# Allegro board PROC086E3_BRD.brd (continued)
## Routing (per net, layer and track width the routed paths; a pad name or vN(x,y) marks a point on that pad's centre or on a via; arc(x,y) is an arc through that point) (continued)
VOUT0_DATA1: length 63.6
  TOP w0.178: v1(73.28,137.35) 72.75,137.88 72.75,139.28 72.28,139.75 U11.4 ; v1(80.02,128.91) 80.02,106.18 81.2,105.01 J1.43
  BOTTOM w0.178: v1(73.28,137.35) 74.47,136.15 75.38,136.15 75.54,136 75.54,134.96 76.02,134.48 78.66,134.48 78.84,134.65 78.84,135.06 78.66,135.24 76.38,135.24 76.2,135.42 76.2,135.84 76.36,136 79.32,136 79.5,135.82 79.5,134.58 78.71,133.79 78.71,133.47 78.56,133.32 76.74,133.32 76.35,132.93 76.35,131.96 76.53,131.78 76.8,131.78 76.96,131.94 76.96,132.11 77.14,132.29 77.49,132.29 77.65,132.14 77.65,131.22 77.8,131.07 78.02,131.07 78.18,131.22 78.18,132.63 78.34,132.78 78.66,132.78 78.84,132.61 78.84,130.88 78.22,130.26 78.22,129.65 78.4,129.47 79.46,129.47 v1(80.02,128.91)
VOUT0_DATA2: length 63.7
  TOP w0.178: U11.6 v1(73.28,138.37) ; J1.41 81.11,104.51 79.5,106.12 79.5,129.48 v1(78.98,130.01)
  BOTTOM w0.178: v1(78.98,130.01) 79.4,130.42 79.4,133.61 79.55,133.76 82.73,133.76 82.91,133.94 82.91,134.53 82.4,135.03 80.49,135.03 80.31,135.21 80.31,136.56 80.14,136.74 75.46,136.74 73.79,138.41 73.79,142.19 73.43,142.55 72.14,142.55 71.96,142.38 71.96,141.91 72.49,141.38 72.49,140.52 71.96,139.99 71.96,138.54 72.14,138.37 v1(73.28,138.37)
VOUT0_DATA3: length 63.7
  TOP w0.178: J1.45 81.43,105.51 80.54,106.4 80.54,131.88 80.7,132.03 81.86,132.03 82.02,132.19 82.02,132.41 81.86,132.57 80.8,132.57 80.37,133 79.1,133 78.92,132.82 78.92,132.51 79.07,132.35 79.83,132.35 79.98,132.2 79.98,131.97 79.83,131.82 79.07,131.82 78.92,131.66 78.92,130.72 79.1,130.54 79.84,130.54 80.02,130.36 v1(80.02,130.01) ; U11.9 v1(74.78,138.37)
  BOTTOM w0.178: v1(74.78,138.37) 75.36,137.78 76.3,137.78 76.76,137.32 79.35,137.32 79.81,137.78 80.9,137.78 81.08,137.6 81.08,135.72 81.25,135.54 82.65,135.54 83.97,134.22 83.97,133.49 83.64,133.16 80.2,133.16 80.02,132.98 v1(80.02,130.01)
VOUT0_DATA4: length 63.4
  TOP w0.178: J1.47 82.57,106.01 80.95,107.63 80.95,128.89 v1(81.06,129) ; U11.11 v1(75.78,138.37)
  BOTTOM w0.178: v1(81.06,129) 81.06,129.97 80.57,130.46 80.57,131.83 81.33,132.6 83.87,132.6 84.94,133.66 84.94,134.12 82.4,136.66 82.4,137.73 81.94,138.18 79.4,138.18 78.94,137.73 77.27,137.73 77.09,137.9 77.09,141.61 76.64,142.06 74.82,142.06 74.27,141.51 74.27,140.37 74.45,140.19 76.25,140.19 76.4,140.03 76.4,139.81 76.25,139.66 74.74,139.66 74.58,139.5 74.58,139.28 74.74,139.12 76.25,139.12 76.4,138.97 76.4,138.54 76.23,138.37 v1(75.78,138.37)
VOUT0_DATA5: length 63.9
  TOP w0.178: U11.13 76.78,139.16 76.85,139.09 76.85,110.85 76.81,110.85 70.28,104.33 70.28,100.29 70.56,100.01 70.88,100.01 71.04,99.85 71.04,99.02 71.19,98.87 71.41,98.87 71.57,99.02 71.57,99.85 71.73,100.01 71.95,100.01 72.1,99.85 72.1,99.02 72.26,98.87 72.48,98.87 72.64,99.02 72.64,99.85 72.79,100.01 73.01,100.01 73.17,99.85 73.17,99.02 73.33,98.87 73.55,98.87 73.7,99.02 73.7,99.85 73.86,100.01 J1.23
VOUT0_DATA6: length 63.5
  TOP w0.178: U11.15 v1(77.78,138.37) ; J1.49 82.73,106.51 81.36,107.87 81.36,128.11 81.69,128.43 81.69,129.32 81.06,129.94 v1(81.06,131.29)
  BOTTOM w0.178: v1(81.06,131.29) 81.31,131.53 83.21,131.53 83.57,131.17 84.53,131.17 84.83,131.47 84.83,131.69 84.51,132 84.51,132.32 84.79,132.6 85.14,132.6 85.42,132.32 85.67,132.32 86.31,132.95 86.31,133.56 83.06,136.81 83.06,141 82.88,141.18 81.53,141.18 81.35,141 81.35,140.65 81.51,140.5 82.29,140.5 82.45,140.34 82.45,140.04 82.27,139.86 81.51,139.86 81.35,139.7 81.35,139.48 81.53,139.3 82.37,139.3 82.53,139.15 82.53,138.92 82.3,138.69 81,138.69 80.82,138.87 80.82,141.07 80.64,141.24 79.98,141.24 79.81,141.07 79.81,139.07 79.63,138.9 78.38,138.9 77.85,138.37 v1(77.78,138.37)
VOUT0_DATA7: length 63.8
  TOP w0.178: U11.18 79.28,138.62 77.23,136.58 77.23,110.59 70.76,104.12 70.76,100.68 70.94,100.51 71.26,100.51 71.42,100.66 71.42,103.46 71.57,103.61 71.79,103.61 71.95,103.46 71.95,100.66 72.11,100.51 J1.25
VOUT0_DATA8: length 63.4
  TOP w0.178: U11.21 80.78,139.48 77.64,136.35 77.64,110.34 72.49,105.19 72.49,101.18 72.67,101.01 73.16,101.01 73.31,101.16 73.31,104.93 73.47,105.09 73.69,105.09 73.85,104.93 73.85,101.16 74,101.01 J1.27
VOUT0_DATA9: length 63.6
  TOP w0.178: J1.29 75.79,101.51 75.63,101.66 75.63,103.48 75.48,103.64 75.25,103.64 75.1,103.48 75.1,101.66 74.94,101.51 74.62,101.51 74.32,101.81 74.32,106.26 78.05,109.98 78.05,133.86 78.51,134.32 79.18,134.32 79.33,134.48 79.33,137.19 79.49,137.35 79.71,137.35 79.87,137.19 79.87,134.48 80.02,134.32 80.42,134.32 80.75,134.65 80.75,138.26 81.78,139.29 U11.23
VOUT0_DATA10: length 63.6
  TOP w0.178: U11.25 82.78,136.86 81.76,135.85 81.76,133.76 81.43,133.43 78.83,133.43 78.45,133.05 78.45,109.35 76.3,107.2 76.3,106.4 76.15,106.25 75.16,106.25 75.01,106.09 75.01,105.87 75.16,105.71 76.15,105.71 76.3,105.56 76.3,105.34 76.15,105.18 75.16,105.18 75.01,105.02 75.01,104.8 75.16,104.65 76.15,104.65 76.3,104.49 76.3,102.19 76.5,101.99 76.82,101.99 76.98,102.15 76.98,105.82 77.13,105.98 77.36,105.98 77.51,105.82 77.51,102.16 77.67,102.01 J1.31
VOUT0_DATA11: length 63.6
  TOP w0.178: U11.27 v1(83.78,138.37) ; J1.14 94.45,97.51 99.82,102.88 v1(99.82,129.9)
  BOTTOM w0.178: v1(99.82,129.9) 100.23,130.31 100.23,131.02 100.08,131.17 99.72,131.17 99.57,131.02 99.57,130.62 99.01,130.06 90.53,130.06 84.79,135.8 84.79,136.66 84.94,136.81 84.94,138.13 84.71,138.37 v1(83.78,138.37)
VOUT0_DATA12: length 63.8
  TOP w0.178: U12.2 v1(86.72,138.37) ; v1(98.77,130.7) 98.77,103.45 93.83,98.51 J1.18
  BOTTOM w0.178: v1(98.77,130.7) 90.84,130.7 86.89,134.66 86.89,134.91 88.29,136.3 88.29,136.81 87.83,137.27 87.58,137.27 87.39,137.08 87.39,136.86 87.58,136.67 87.58,136.45 87.42,136.29 87.2,136.29 86.94,136.56 86.71,136.56 86.46,136.3 86.46,136.05 86.67,135.84 86.67,135.62 86.51,135.47 86.18,135.47 85.5,136.15 85.5,136.41 86.94,137.85 86.94,138.07 86.72,138.28 v1(86.72,138.37)
VOUT0_DATA13: length 63.8
  TOP w0.178: U12.4 v1(87.72,138.37) ; J1.16 94.04,98.01 99.29,103.26 v1(99.29,131.73)
  BOTTOM w0.178: v1(99.29,131.73) 99.19,131.63 92.71,131.63 89.62,134.72 89.4,134.72 89.15,134.48 89.15,134.21 90.69,132.68 90.69,132.46 90.5,132.26 90.25,132.26 88.49,134.02 88.49,134.56 89.02,135.1 89.02,135.32 88.7,135.64 88.7,135.9 89.32,136.52 89.32,136.77 v1(87.72,138.37)
VOUT0_DATA14: length 63.8
  TOP w0.178: U12.6 v1(88.72,138.37) ; v1(100.34,132.76) 100.34,102.46 94.39,96.51 J1.10
  BOTTOM w0.178: v1(100.34,132.76) 94.63,132.76 91.32,136.07 91.1,136.07 90.8,135.77 90.8,135.52 91.81,134.51 91.81,134.29 91.57,134.04 91.31,134.04 90.07,135.29 90.07,135.79 90.72,136.45 90.72,136.67 89.02,138.37 v1(88.72,138.37)
VOUT0_DATA15: length 63.7
  TOP w0.178: J1.8 94.6,96.01 100.86,102.27 v1(100.86,133.79) ; U12.9 v1(90.22,138.37)
  BOTTOM w0.178: v1(90.22,138.37) 90.24,138.37 93.07,135.54 94.28,135.54 94.54,135.29 94.54,134.48 95.07,133.94 97.92,133.94 98.08,134.1 98.08,136.34 98.35,136.61 99.26,136.61 99.68,136.19 99.68,134.12 99.86,133.94 100.71,133.94 v1(100.86,133.79)
VOUT0_DATA16: length 63.8
  TOP w0.178: U12.11 v1(91.22,138.37) ; v1(96.19,136.41) 97,135.59 97,106.76 94.75,104.51 J1.42
  BOTTOM w0.178: v1(96.19,136.41) 93.68,136.41 93.5,136.58 93.5,139.96 93.32,140.14 91.18,140.14 91.02,140.3 91.02,141.03 90.87,141.18 90.65,141.18 90.49,141.03 90.49,140.3 90.33,140.14 90.11,140.14 89.96,140.3 89.96,141.03 89.8,141.18 89.58,141.18 89.42,141.03 89.42,140.3 89.27,140.14 85.62,140.14 85.45,139.96 85.45,139.51 85.62,139.33 91.03,139.33 91.22,139.14 v1(91.22,138.37)
VOUT0_DATA17: length 63.6
  TOP w0.178: U12.13 92.22,137.46 92.06,137.3 90.5,137.3 90.35,137.14 90.35,136.92 90.5,136.77 92.06,136.77 92.22,136.61 92.22,136.39 92.06,136.23 90.5,136.23 90.35,136.08 90.35,135.86 90.5,135.7 92.06,135.7 92.22,135.54 92.22,135.32 92.06,135.17 90.5,135.17 90.35,135.01 90.35,134.79 90.5,134.63 92.06,134.63 92.22,134.48 92.22,134.26 92.06,134.1 90.5,134.1 90.35,133.94 90.35,133.72 90.5,133.57 92.06,133.57 92.22,133.41 92.22,133.19 92.06,133.03 90.5,133.03 90.35,132.88 90.35,132.66 90.5,132.5 92.06,132.5 92.22,132.34 92.22,132.12 92.06,131.97 90.5,131.97 90.35,131.81 90.35,131.59 90.5,131.43 92.06,131.43 92.22,131.28 92.22,131.06 92.06,130.9 90.5,130.9 90.35,130.74 90.35,130.52 90.5,130.37 92.06,130.37 92.22,130.21 92.22,129.81 92.46,129.57 94.89,129.57 95.2,129.27 95.2,107.79 93.92,106.51 J1.50
VOUT0_DATA18: length 63.7
  TOP w0.178: J1.46 94.34,105.51 96.14,107.31 96.14,134.83 95.89,135.09 95.22,135.09 95.05,134.91 95.05,130.26 94.82,130.03 92.89,130.03 92.71,130.21 92.71,130.96 92.87,131.12 94.18,131.12 94.34,131.28 94.34,131.5 94.18,131.65 92.87,131.65 92.71,131.81 92.71,132.03 92.87,132.19 94.18,132.19 94.34,132.34 94.34,132.56 94.18,132.72 92.87,132.72 92.71,132.88 92.71,133.1 92.87,133.25 94.18,133.25 94.34,133.41 94.34,133.63 94.18,133.79 92.87,133.79 92.71,133.94 92.71,134.16 92.87,134.32 94.18,134.32 94.34,134.48 94.34,134.7 94.18,134.85 92.87,134.85 92.71,135.01 92.71,138.74 93.22,139.25 U12.15
VOUT0_DATA19: length 63.7
  TOP w0.178: v1(97.61,128.28) 97.43,128.46 97.43,136.91 94.72,139.63 U12.18 ; J1.40 v1(92.64,104.01)
  BOTTOM w0.178: v1(92.64,104.01) 93.74,104.01 97.43,107.7 97.43,118.06 97.28,118.21 96.19,118.21 96.04,118.37 96.04,118.59 96.19,118.74 97.28,118.74 97.43,118.9 97.43,119.12 97.28,119.28 96.19,119.28 96.04,119.43 96.04,119.66 96.19,119.81 97.28,119.81 97.43,119.97 97.43,120.19 97.28,120.35 96.19,120.35 96.04,120.5 96.04,120.72 96.19,120.88 97.28,120.88 97.43,121.03 97.43,121.26 97.28,121.41 96.19,121.41 96.04,121.57 96.04,121.79 96.19,121.95 97.28,121.95 97.43,122.1 97.43,122.32 97.28,122.48 96.19,122.48 96.04,122.63 96.04,122.86 96.19,123.01 97.28,123.01 97.43,123.17 97.43,123.39 97.28,123.55 96.19,123.55 96.04,123.7 96.04,123.92 96.19,124.08 97.28,124.08 97.43,124.24 97.43,124.46 97.28,124.61 96.19,124.61 96.04,124.77 96.04,124.99 96.19,125.15 97.28,125.15 97.43,125.3 97.43,125.52 97.28,125.68 96.19,125.68 96.04,125.84 96.04,126.06 96.19,126.21 97.28,126.21 97.43,126.37 97.43,126.59 97.28,126.75 96.19,126.75 96.04,126.9 96.04,127.12 96.19,127.28 97.28,127.28 97.43,127.44 97.43,128.1 v1(97.61,128.28)
VOUT0_DATA20: length 63.8
  TOP w0.178: U12.21 v1(96.22,139.53) ; v1(96.22,137.4) 95.63,136.81 95.63,136.05 96.57,135.11 96.57,107.04 94.54,105.01 J1.44
  BOTTOM w0.178: v1(96.22,139.53) 96.22,144.53 95.71,145.04 89.48,145.04 89.31,144.86 89.31,144.64 89.46,144.48 94.64,144.48 95.2,143.92 95.2,141.44 95.5,141.13 95.5,138.84 96.22,138.13 96.22,137.4 v1(96.22,137.4)
VOUT0_DATA21: length 63.8
  TOP w0.178: J1.48 94.13,106.01 95.63,107.51 v1(95.63,134.5) ; U12.23 v1(97.22,139.53)
  BOTTOM w0.178: v1(97.22,139.53) 97.22,146.13 97.37,146.29 98.04,146.29 98.22,146.11 98.22,146.02 98.38,145.87 99.26,145.87 99.42,145.71 99.42,145.49 99.26,145.33 98.38,145.33 98.18,145.13 98.18,142.32 98.38,142.13 100.05,142.13 100.2,141.97 100.2,141.75 100.05,141.59 98.38,141.59 98.22,141.44 98.22,141.21 98.38,141.06 100.05,141.06 100.2,140.9 100.2,140.68 100.05,140.52 98.38,140.52 98.22,140.37 98.22,139.15 98.04,138.97 97.66,138.97 97.22,138.53 97.22,134.68 97.04,134.5 v1(95.63,134.5)
VOUT0_DATA22: length 63.8
  TOP w0.178: J1.28 92.34,101.01 v1(92.74,101.41) ; U12.25 98.22,139.51 98.27,139.45 98.27,134.25 v1(99.11,133.41)
  BOTTOM w0.178: v1(99.11,133.41) 100.43,133.41 100.86,132.98 100.86,128.13 100.71,127.97 99.83,127.97 99.67,127.82 99.67,127.6 99.83,127.44 100.71,127.44 100.86,127.28 100.86,127.06 100.71,126.91 99.83,126.91 99.67,126.75 99.67,126.53 99.83,126.37 100.71,126.37 100.86,126.22 100.86,126 100.71,125.84 99.83,125.84 99.67,125.68 99.67,125.46 99.83,125.31 100.71,125.31 100.86,125.15 100.86,124.93 100.71,124.77 99.83,124.77 99.67,124.62 99.67,124.4 99.83,124.24 100.71,124.24 100.86,124.08 100.86,123.86 100.71,123.71 99.83,123.71 99.67,123.55 99.67,123.33 99.83,123.17 100.71,123.17 100.86,123.02 100.86,122.8 100.71,122.64 99.83,122.64 99.67,122.48 99.67,122.26 99.83,122.11 100.71,122.11 100.86,121.95 100.86,121.73 100.71,121.57 99.83,121.57 99.67,121.42 99.67,121.19 99.83,121.04 100.71,121.04 100.86,120.88 100.86,120.66 100.71,120.51 99.83,120.51 99.67,120.35 99.67,120.13 99.83,119.97 100.71,119.97 100.86,119.82 100.86,106.84 95.43,101.41 v1(92.74,101.41)
VOUT0_DATA23: length 63.8
  TOP w0.178: U12.27 v1(99.22,139.53) ; v1(97.74,138.24) 97.87,138.11 97.87,129.12 98.3,128.68 98.3,127.77 97.87,127.34 97.87,104.88 94.99,102.01 J1.32
  BOTTOM w0.178: v1(97.74,138.24) 101.07,138.24 101.32,138.49 101.32,146.67 101.14,146.85 100.81,146.85 100.63,146.67 100.63,139.73 100.43,139.53 v1(99.22,139.53)
VOUT0_DE: length 63.6
  TOP w0.178: U10.6 57.71,139.55 59.61,137.65 62.36,137.65 62.69,137.32 62.69,136.74 v1(63.3,136.13) ; J1.34 v1(89.66,102.51)
  L03_SIG1 w0.107: v1(89.66,102.51) 89.27,102.51 87.22,104.55 87.22,115.39 83.77,118.84 77.06,118.84 76.95,118.94 76.95,119.34 76.84,119.44 76.39,119.44 76.28,119.34 76.28,118.94 76.18,118.84 70.45,118.84 69.9,119.39 69.9,123.25 64.75,128.4 64.75,134.67 v1(63.3,136.13)
VOUT0_EXTPCLKIN: length 63.6
  TOP w0.178: J1.21 82.89,99.51 v1(82.85,99.47) ; v1(62.13,136.13) 56.29,136.13 55.71,136.7 U10.2
  L08_SIG2 w0.107: v1(82.85,99.47) 73.56,108.77 73.56,110.44 73.65,110.53 74.23,110.53 74.32,110.63 74.32,110.76 74.23,110.85 73.65,110.85 73.56,110.95 73.56,111.08 73.65,111.17 74.23,111.17 74.32,111.27 74.32,111.4 74.23,111.49 73.65,111.49 73.56,111.59 73.56,111.72 73.65,111.81 74.23,111.81 74.32,111.91 74.32,112.04 74.23,112.13 73.65,112.13 73.56,112.23 73.56,112.36 73.65,112.45 74.23,112.45 74.32,112.55 74.32,112.68 74.23,112.77 73.65,112.77 73.56,112.87 73.56,120.51 71.83,122.23 71.83,122.64 71.02,123.45 70.61,123.45 66.6,127.47 66.6,131.48 62.13,135.95 v1(62.13,136.13)
VOUT0_HSYNC: length 63.6
  TOP w0.178: v1(62.13,137.14) 59.21,137.14 56.72,139.63 56.72,140.68 U10.4 ; J1.12 v1(90.07,97.01)
  L03_SIG1 w0.107: v1(90.07,97.01) 90.17,97.11 90.17,110.45 88.44,112.17 88.44,114.64 83.86,119.23 81.09,119.23 63.8,136.51 63.8,137.32 63.49,137.64 62.62,137.64 v1(62.13,137.14)
VOUT0_PCLK: length 63.7
  TOP w0.178: v1(94.77,102.52) 93.43,102.52 92.94,103.01 J1.36 ; v1(67.46,138.29) 67.46,138.74 68.21,139.49 U10.27
  L03_SIG1 w0.107: v1(94.77,102.52) 94.03,103.26 94.03,123.86 91.9,125.99 91.9,128.79 84.73,135.95 73.76,135.95 73.05,135.24 69.01,135.24 68.33,135.92 68.33,137.42 v1(67.46,138.29)
VOUT0_VSYNC: length 63.8
  TOP w0.178: J1.33 v1(84.03,102.51) ; v1(63.3,137.14) 63.3,137.5 62.76,138.03 60.33,138.03 59.21,139.14 U10.9
  L03_SIG1 w0.107: v1(63.3,137.14) 62.74,136.58 62.74,134.32 62.18,133.76 62.18,127.97 63.6,126.55 63.6,121.88 67.01,118.47 83.69,118.47 86.56,115.6 86.56,105.04 v1(84.03,102.51)
VOUTEXP_INTB: length 118.1
  TOP w0.178: J2.17 83.19,49.13 83.19,49.13 v1(83.12,49.13)
  L08_SIG2 w0.107: v1(65.21,131.94) 66.19,130.96 66.19,126.86 71.78,121.27 71.78,107.07 82.42,96.43 82.42,57.26 81.03,55.86 81.03,52.59 82.11,51.51 82.11,50.15 v1(83.12,49.13)
  BOTTOM w0.178: v1(65.21,131.94) 68.07,134.79 68.07,139.15 65.89,141.33 TP124.1 65.89,147 66.75,147.86 R354.2 U43.22
VOUTEXP_P04: length 3.2
  BOTTOM w0.178: U43.6 65,158.91 TP34.1
VOUTEXP_P05: length 2
  BOTTOM w0.178: TP33.1 U43.7
VOUTEXP_P16: length 2.5
  BOTTOM w0.178: TP38.1 70.46,156.29 70.08,155.91 U43.16
VOUTEXP_P17: length 4.5
  BOTTOM w0.178: U43.17 TP39.1
VPFE0_DATA0: length 55.1
  TOP w0.178: U12.44 v1(92.22,147.03) ; R37.1 57.37,163.52 v1(57.38,163.51)
  L03_SIG1 w0.107: v1(57.38,163.51) 58.39,162.49 65.02,162.49 65.35,162.82 71.63,162.82 72.03,162.42 72.03,160.31 79.37,152.98 80.81,152.98 80.9,152.88 80.9,152.65 80.99,152.56 81.13,152.56 81.22,152.65 81.22,152.88 81.31,152.98 86.36,152.98 86.45,153.07 86.58,153.07 86.68,152.98 86.68,152.53 86.77,152.43 86.9,152.43 87,152.53 87,152.98 87.09,153.07 87.22,153.07 87.32,152.98 87.32,152.53 87.41,152.43 87.54,152.43 87.64,152.53 87.64,152.98 87.73,153.07 87.86,153.07 87.96,152.98 87.96,152.53 88.05,152.43 88.18,152.43 88.28,152.53 88.28,152.98 88.37,153.07 88.5,153.07 88.6,152.98 88.6,152.53 88.69,152.43 88.82,152.43 88.92,152.53 88.92,152.98 89.01,153.07 89.14,153.07 89.24,152.98 89.24,152.53 89.33,152.43 89.46,152.43 89.56,152.53 89.56,152.98 89.65,153.07 89.78,153.07 89.88,152.98 89.88,152.53 89.97,152.43 90.1,152.43 90.2,152.53 90.2,152.98 90.29,153.07 90.42,153.07 90.52,152.98 90.52,152.53 90.61,152.43 91.49,152.43 92.22,151.71 v1(92.22,147.03)
VPFE0_DATA1: length 55.6
  TOP w0.178: v1(58.62,163.51) 58.61,163.52 R38.1 ; U12.42 v1(93.22,147.03)
  L03_SIG1 w0.107: v1(93.22,147.03) 93.22,151.52 91.14,153.6 86.16,153.6 86.07,153.7 86.07,154.19 85.98,154.29 85.84,154.29 85.75,154.19 85.75,153.7 85.66,153.6 85.52,153.6 85.43,153.7 85.43,154.19 85.34,154.29 85.2,154.29 85.11,154.19 85.11,153.7 85.02,153.6 84.88,153.6 84.79,153.7 84.79,154.19 84.7,154.29 84.56,154.29 84.47,154.19 84.47,153.7 84.38,153.6 84.24,153.6 84.15,153.7 84.15,154.19 84.06,154.29 83.92,154.29 83.83,154.19 83.83,153.7 83.74,153.6 83.6,153.6 83.51,153.7 83.51,154.19 83.42,154.29 83.28,154.29 83.19,154.19 83.19,153.7 83.1,153.6 82.96,153.6 82.87,153.7 82.87,154.19 82.78,154.29 82.64,154.29 82.55,154.19 82.55,153.7 82.46,153.6 82.32,153.6 82.23,153.7 82.23,154.19 82.14,154.29 82,154.29 81.91,154.19 81.91,153.7 81.82,153.6 81.28,153.6 80.48,154.4 79.51,154.4 73.94,159.98 73.94,162.14 72.9,163.18 65.07,163.18 64.74,162.85 59.28,162.85 v1(58.62,163.51)
VPFE0_DATA2: length 55.7
  TOP w0.178: R33.1 v1(52.39,163.58) ; U12.40 v1(94.22,147.03)
  L03_SIG1 w0.107: v1(52.39,163.58) 52.86,163.1 53.85,163.1 54.97,164.22 58.83,164.22 59.82,163.23 64.52,163.23 64.82,163.53 73.01,163.53 74.35,162.2 74.35,160.03 79.4,154.97 90.81,154.97 94.22,151.56 v1(94.22,147.03)
VPFE0_DATA3: length 55.2
  TOP w0.178: R34.1 v1(53.63,163.58) ; U12.37 v1(95.72,147.03)
  L03_SIG1 w0.107: v1(53.63,163.58) 54.6,164.55 59.41,164.55 60.33,163.64 62.66,163.64 62.92,163.89 73.12,163.89 74.85,162.16 74.85,160.03 79.53,155.35 91.08,155.35 95.72,150.72 v1(95.72,147.03)
VPFE0_DATA4: length 54.9
  TOP w0.178: v1(62.38,164.12) 61.52,163.25 60.34,163.25 59.86,163.74 R39.1 ; U12.35 v1(96.72,147.03)
  L03_SIG1 w0.107: v1(96.72,147.03) 96.72,155.51 96.44,155.79 95.72,155.79 95.63,155.88 95.63,156.4 95.53,156.5 95.4,156.5 95.31,156.4 95.31,155.88 95.21,155.79 95.08,155.79 94.99,155.88 94.99,156.4 94.89,156.5 94.76,156.5 94.67,156.4 94.67,155.88 94.57,155.79 79.6,155.79 75.21,160.18 75.21,162.31 73.28,164.24 62.51,164.24 v1(62.38,164.12)
VPFE0_DATA5: length 55.6
  TOP w0.178: R40.1 61.51,164.31 v1(61.93,164.73) ; U12.33 v1(97.72,147.03)
  L03_SIG1 w0.107: v1(61.93,164.73) 62.05,164.6 72.85,164.6 73.1,164.85 79.4,164.85 86.84,157.41 91.32,157.41 91.42,157.51 91.42,157.98 91.51,158.07 91.64,158.07 91.74,157.98 91.74,157.51 91.83,157.41 91.96,157.41 92.06,157.51 92.06,157.98 92.15,158.07 92.28,158.07 92.38,157.98 92.38,157.51 92.47,157.41 92.6,157.41 92.7,157.51 92.7,157.98 92.79,158.07 92.92,158.07 93.02,157.98 93.02,157.51 93.11,157.41 93.24,157.41 93.34,157.51 93.34,157.98 93.43,158.07 93.56,158.07 93.66,157.98 93.66,157.51 93.75,157.41 97.09,157.41 97.72,156.78 v1(97.72,147.03)
VPFE0_DATA6: length 55.7
  TOP w0.178: v1(61.05,152.97) 61.2,153.12 61.45,153.12 62.21,152.36 U10.42 ; R35.1 v1(54.88,163.32)
  L08_SIG2 w0.107: v1(54.88,163.32) 55.83,162.37 57.53,162.37 57.63,162.26 57.63,161.86 57.54,161.77 55.49,161.77 55.4,161.68 55.4,161.54 55.49,161.45 57.84,161.45 57.94,161.36 57.94,161.22 57.84,161.13 55.49,161.13 55.4,161.04 55.4,160.9 55.49,160.81 57.84,160.81 57.94,160.72 57.94,160.58 57.84,160.49 55.49,160.49 55.4,160.4 55.4,160.26 55.49,160.17 57.84,160.17 57.94,160.08 57.94,159.94 57.84,159.85 55.49,159.85 55.4,159.76 55.4,159.62 55.49,159.53 57.84,159.53 57.94,159.44 57.94,159.3 57.84,159.21 55.49,159.21 55.4,159.12 55.4,158.98 55.49,158.89 57.84,158.89 57.94,158.8 57.94,158.66 57.84,158.57 55.49,158.57 55.4,158.48 55.4,158.34 55.49,158.25 57.84,158.25 57.94,158.16 57.94,158.02 57.84,157.93 55.49,157.93 55.4,157.84 55.4,157.7 55.49,157.61 57.84,157.61 57.94,157.52 57.94,153.79 58.04,153.68 58.88,153.68 59.28,153.27 60.94,153.27 61.05,153.17 v1(61.05,152.97)
VPFE0_DATA7: length 55.1
  TOP w0.178: U10.40 63.21,152.31 v1(62.23,153.3) ; R36.1 v1(56.12,163.32)
  L08_SIG2 w0.107: v1(56.12,163.32) 56.6,162.85 58.62,162.85 58.72,162.74 58.72,162.65 58.82,162.56 60.05,162.56 60.15,162.47 60.15,162.33 60.05,162.24 58.82,162.24 58.72,162.15 58.72,162.01 58.82,161.92 60.05,161.92 60.15,161.83 60.15,161.69 60.05,161.6 58.82,161.6 58.72,161.51 58.72,161.37 58.82,161.28 60.05,161.28 60.15,161.19 60.15,161.05 60.05,160.96 58.82,160.96 58.72,160.87 58.72,160.73 58.82,160.64 60.05,160.64 60.15,160.55 60.15,160.41 60.05,160.32 58.82,160.32 58.72,160.23 58.72,160.09 58.82,160 60.05,160 60.15,159.91 60.15,159.77 60.05,159.68 58.82,159.68 58.72,159.59 58.72,159.45 58.82,159.36 60.05,159.36 60.15,159.27 60.15,159.13 60.05,159.04 58.82,159.04 58.72,158.95 58.72,158.81 58.82,158.72 60.05,158.72 60.15,158.63 60.15,158.49 60.05,158.4 58.82,158.4 58.72,158.31 58.72,158.17 58.82,158.08 60.05,158.08 60.15,157.99 60.15,157.85 60.05,157.76 58.82,157.76 58.72,157.67 58.72,157.53 58.82,157.44 60.05,157.44 60.15,157.35 60.15,157.21 60.05,157.12 58.82,157.12 58.72,157.03 58.72,156.89 58.82,156.8 60.05,156.8 60.15,156.71 60.15,156.57 60.05,156.48 58.82,156.48 58.72,156.39 58.72,156.25 58.82,156.16 60.05,156.16 60.15,156.07 60.15,155.93 60.05,155.84 58.82,155.84 58.72,155.75 58.72,155.61 58.82,155.52 60.05,155.52 60.15,155.43 60.15,155.29 60.05,155.2 58.82,155.2 58.72,155.11 58.72,154.97 58.82,154.88 60.05,154.88 60.15,154.79 60.15,154.65 60.05,154.56 59.33,154.56 59.18,154.41 59.18,154.01 59.34,153.86 61.67,153.86 v1(62.23,153.3)
VPFE0_DATA8: length 56.8
  TOP w0.178: R45.1 v1(70.26,161.76) ; U12.51 v1(88.72,147.03)
  L03_SIG1 w0.107: v1(70.26,161.76) 70.26,161.17 79.65,151.77 84.41,151.77 84.5,151.68 84.5,150.9 84.59,150.81 84.73,150.81 84.82,150.9 84.82,151.68 84.91,151.77 85.05,151.77 85.14,151.68 85.14,150.9 85.23,150.81 85.37,150.81 85.46,150.9 85.46,151.68 85.55,151.77 85.69,151.77 85.78,151.68 85.78,150.9 85.87,150.81 86.01,150.81 86.1,150.9 86.1,151.68 86.19,151.77 86.33,151.77 86.42,151.68 86.42,150.9 86.51,150.81 86.65,150.81 86.74,150.9 86.74,151.68 86.83,151.77 87.05,151.77 87.15,151.68 87.15,150.93 87.24,150.83 87.37,150.83 87.47,150.93 87.47,151.68 87.56,151.77 87.96,151.77 88.72,151.01 88.72,150.44 88.62,150.34 88.22,150.34 88.12,150.44 88.12,151.04 88.03,151.14 87.9,151.14 87.8,151.04 87.8,150.44 87.71,150.34 86.77,150.34 86.68,150.25 86.68,150.12 86.77,150.02 88.62,150.02 88.72,149.93 88.72,149.8 88.62,149.7 86.77,149.7 86.68,149.61 86.68,149.48 86.77,149.38 88.62,149.38 88.72,149.29 88.72,149.16 88.62,149.06 86.77,149.06 86.68,148.97 86.68,148.84 86.77,148.74 88.62,148.74 88.72,148.65 88.72,148.52 88.62,148.42 86.77,148.42 86.68,148.33 86.68,148.15 86.79,148.04 87.6,148.04 87.7,147.93 87.7,147.37 87.8,147.28 87.98,147.28 88.09,147.38 88.09,148.01 88.18,148.1 88.62,148.1 88.72,148.01 v1(88.72,147.03)
VPFE0_DATA9: length 57.9
  TOP w0.178: U12.46 v1(91.22,147.03) ; R46.1 v1(71.42,161.76)
  L03_SIG1 w0.107: v1(71.42,161.76) 71.42,160.46 79.78,152.1 83.22,152.1 83.32,152.2 83.32,152.52 83.41,152.61 83.54,152.61 83.64,152.52 83.64,152.2 83.73,152.1 83.86,152.1 83.96,152.2 83.96,152.52 84.05,152.61 84.18,152.61 84.28,152.52 84.28,152.2 84.37,152.1 84.5,152.1 84.6,152.2 84.6,152.52 84.69,152.61 84.82,152.61 84.92,152.52 84.92,152.2 85.01,152.1 85.14,152.1 85.24,152.2 85.24,152.52 85.33,152.61 85.46,152.61 85.56,152.52 85.56,152.2 85.65,152.1 88.46,152.1 88.55,152.01 88.55,151.66 88.64,151.57 88.78,151.57 88.87,151.66 88.87,152.01 88.96,152.1 89.1,152.1 89.19,152.01 89.19,151.66 89.28,151.57 89.42,151.57 89.51,151.66 89.51,152.01 89.6,152.1 89.74,152.1 89.83,152.01 89.83,151.66 89.92,151.57 90.06,151.57 90.15,151.66 90.15,152.01 90.24,152.1 91.03,152.1 91.22,151.92 91.22,150.53 91.12,150.44 89.22,150.44 89.13,150.34 89.13,150.21 89.22,150.12 91.12,150.12 91.22,150.02 91.22,149.89 91.12,149.8 89.22,149.8 89.13,149.7 89.13,149.57 89.22,149.48 91.12,149.48 91.22,149.38 91.22,149.25 91.12,149.16 89.22,149.16 89.13,149.06 89.13,148.93 89.22,148.84 91.12,148.84 91.22,148.74 91.22,148.61 91.12,148.52 89.22,148.52 89.13,148.42 89.13,148.29 89.22,148.2 91.12,148.2 91.22,148.1 91.22,147.97 91.12,147.88 89.22,147.88 89.13,147.78 89.13,147.65 89.22,147.56 91.12,147.56 91.22,147.46 v1(91.22,147.03)
VPFE0_DATA10: length 55.5
  TOP w0.178: U10.48 59.21,151.45 v1(59.74,151.98) ; v1(62.81,161.25) 63.2,161.63 R41.1
  L08_SIG2 w0.107: v1(59.74,151.98) 59.8,151.98 60.2,152.38 63.14,152.38 63.25,152.49 63.25,154.18 63.15,154.27 60.75,154.27 60.66,154.37 60.66,154.5 60.75,154.59 63.15,154.59 63.25,154.69 63.25,154.82 63.15,154.91 60.75,154.91 60.66,155.01 60.66,155.14 60.75,155.23 63.15,155.23 63.25,155.33 63.25,155.46 63.15,155.55 60.75,155.55 60.66,155.65 60.66,155.78 60.75,155.87 63.15,155.87 63.25,155.97 63.25,156.1 63.15,156.19 60.75,156.19 60.66,156.29 60.66,156.42 60.75,156.51 63.15,156.51 63.25,156.61 63.25,156.74 63.15,156.83 60.75,156.83 60.66,156.93 60.66,157.06 60.75,157.15 63.15,157.15 63.25,157.25 63.25,157.38 63.15,157.47 60.75,157.47 60.66,157.57 60.66,157.7 60.75,157.79 60.98,157.79 61.07,157.89 61.07,158.49 61.16,158.58 61.3,158.58 61.39,158.49 61.39,157.89 61.48,157.79 63.15,157.79 63.25,157.89 63.25,158.67 63.25,158.67 63.25,159.05 63.25,159.05 63.25,160.09 63.15,160.18 60.77,160.18 60.68,160.27 60.68,160.41 60.77,160.5 63.03,160.5 63.12,160.59 63.12,160.94 v1(62.81,161.25)
VPFE0_DATA11: length 55.5
  TOP w0.178: U10.37 64.71,153.48 v1(64.16,154.03) ; R42.1 v1(64.36,161.32)
  L08_SIG2 w0.107: v1(64.36,161.32) 65.58,160.1 68.02,160.1 68.12,160 68.12,159.59 68.03,159.5 67.3,159.5 67.21,159.4 67.21,159.27 67.3,159.18 68.73,159.18 68.82,159.08 68.82,158.95 68.73,158.86 67.3,158.86 67.21,158.76 67.21,158.63 67.3,158.54 68.73,158.54 68.82,158.44 68.82,158.31 68.73,158.22 67.3,158.22 67.21,158.12 67.21,157.99 67.3,157.9 68.71,157.9 68.82,157.79 68.82,155.95 68.92,155.86 70.34,155.86 70.43,155.77 70.43,155.63 70.34,155.54 68.92,155.54 68.82,155.45 68.82,155.31 68.92,155.22 70.34,155.22 70.43,155.13 70.43,154.99 70.34,154.9 68.92,154.9 68.82,154.8 68.82,154.2 68.66,154.03 67.83,154.03 67.73,153.94 67.73,151.82 67.64,151.72 67.51,151.72 67.41,151.82 67.41,153.94 67.32,154.03 67.19,154.03 67.09,153.94 67.09,151.82 67,151.72 66.87,151.72 66.77,151.82 66.77,153.94 66.68,154.03 65.74,154.03 65.65,153.94 65.65,151.82 65.55,151.72 65.42,151.72 65.33,151.82 65.33,153.94 65.23,154.03 65.1,154.03 65.01,153.94 65.01,151.82 64.91,151.72 64.78,151.72 64.69,151.82 64.69,153.94 64.59,154.03 v1(64.16,154.03)
VPFE0_DATA12: length 65.4
  TOP w0.178: R532.1 65.53,163.13 65,162.59 v1(65,162.01) ; v1(63.73,154.9) 64.47,154.9 65.48,153.88 65.48,150.99 66.19,150.27 66.19,149.61 65.71,149.13 U10.35
  L08_SIG2 w0.107: v1(63.73,154.9) 64.17,154.9 64.77,155.5 64.77,157.16 64.35,157.58 64.05,157.58 63.96,157.68 63.96,157.81 64.05,157.9 64.35,157.9 64.44,158 64.44,158.13 64.35,158.22 64.05,158.22 63.96,158.32 63.96,158.45 64.05,158.54 64.46,158.54 64.57,158.65 64.57,159.1 64.46,159.2 63.82,159.2 63.72,159.31 63.72,161.82 63.53,162.01 62.18,162.01 62.08,161.92 62.08,160.96 61.99,160.87 61.86,160.87 61.76,160.96 61.76,161.92 61.67,162.01 61.54,162.01 61.44,161.92 61.44,160.96 61.35,160.87 61.04,160.87 60.91,160.99 60.91,164.09 61.04,164.22 61.74,164.22 61.83,164.13 61.83,162.51 61.92,162.42 62.29,162.42 62.38,162.51 62.38,163.52 62.48,163.61 62.61,163.61 62.7,163.52 62.7,162.51 62.8,162.42 63.02,162.42 63.11,162.51 63.11,164 63.2,164.09 63.34,164.09 63.43,164 63.43,162.51 63.52,162.42 63.66,162.42 63.75,162.51 63.75,164 63.84,164.09 63.98,164.09 64.07,164 64.07,162.51 64.16,162.42 64.3,162.42 64.39,162.51 64.39,164 64.49,164.09 64.71,164.09 64.8,164 64.8,163.2 64.89,163.1 65.03,163.1 65.12,163.2 65.12,164 65.21,164.09 65.35,164.09 65.44,164 65.44,163.2 65.53,163.1 65.67,163.1 65.76,163.2 65.76,164 65.85,164.09 65.99,164.09 66.08,164 66.08,163.2 66.17,163.1 66.31,163.1 66.4,163.2 66.4,164 66.49,164.09 66.63,164.09 66.72,164 66.72,163.2 66.81,163.1 66.95,163.1 67.04,163.2 67.04,164 67.13,164.09 67.27,164.09 67.36,164 67.36,163.2 67.45,163.1 67.59,163.1 67.68,163.2 67.68,164 67.77,164.09 67.91,164.09 68,164 68,163.2 68.09,163.1 68.23,163.1 68.32,163.2 68.32,164 68.41,164.09 68.56,164.09 68.67,163.99 68.67,162.9 68.56,162.8 65.16,162.8 65,162.64 v1(65,162.01)
VPFE0_DATA13: length 65.7
  TOP w0.178: R533.1 66.75,163.38 v1(65.68,162.31) ; U11.44 76.78,152.87 76.95,153.04 v1(77.52,153.04)
  L03_SIG1 w0.107: v1(65.68,162.31) 69.49,162.31 69.7,162.11 69.7,160.54 71.75,158.48 71.75,157.43 71.85,157.33 72.83,157.33 72.92,157.24 72.92,157.11 72.83,157.01 71.85,157.01 71.75,156.92 71.75,156.79 71.85,156.69 72.83,156.69 72.92,156.6 72.92,156.47 72.83,156.37 71.85,156.37 71.75,156.28 71.75,156.15 71.85,156.05 72.83,156.05 72.92,155.96 72.92,155.83 72.83,155.73 71.85,155.73 71.75,155.64 71.75,155.51 71.85,155.41 72.83,155.41 72.92,155.32 72.92,155.19 72.83,155.09 71.85,155.09 71.75,155 71.75,154.14 71.86,154.03 72.24,154.03 72.33,153.94 72.33,153.37 72.42,153.28 72.56,153.28 72.65,153.37 72.65,153.94 72.74,154.03 72.96,154.03 73.06,153.94 73.06,152.65 73.15,152.55 73.28,152.55 73.38,152.65 73.38,153.94 73.47,154.03 73.69,154.03 73.79,153.94 73.79,152.53 73.88,152.43 74.14,152.43 74.24,152.54 74.24,153.93 74.35,154.03 74.58,154.03 74.67,153.94 74.67,152.6 74.77,152.51 75.05,152.51 75.16,152.62 75.16,154.89 75.37,155.1 75.59,155.1 75.79,154.89 75.79,153.26 75.89,153.17 76.97,153.17 77.06,153.07 77.06,152.94 76.97,152.85 75.89,152.85 75.79,152.75 75.79,152.62 75.89,152.53 76.97,152.53 77.06,152.43 77.06,152.3 76.97,152.21 75.89,152.21 75.79,152.11 75.79,151.98 75.89,151.89 76.97,151.89 77.06,151.79 77.06,151.66 76.97,151.57 75.89,151.57 75.79,151.47 75.79,150.33 75.9,150.22 76.12,150.22 76.21,150.32 76.21,151.15 76.31,151.24 76.44,151.24 76.54,151.15 76.54,150.32 76.63,150.22 76.76,150.22 76.86,150.32 76.86,151.15 76.95,151.24 77.08,151.24 77.18,151.15 77.18,150.32 77.27,150.22 77.72,150.22 77.9,150.4 77.9,151.06 78.03,151.19 78.17,151.19 78.28,151.3 78.28,151.48 78.15,151.61 78,151.61 77.9,151.7 77.9,151.92 78,152.01 78.34,152.01 78.43,152.11 78.43,152.24 78.34,152.33 78,152.33 77.9,152.43 77.9,152.94 77.8,153.04 v1(77.52,153.04)
VPFE0_HD: length 54.1
  TOP w0.178: U11.53 v1(72.28,152.11) ; R43.1 v1(67.92,161.57)
  L03_SIG1 w0.107: v1(67.92,161.57) 67.89,161.6 65.23,161.6 64.82,161.2 64.82,160.13 65.07,159.88 69.34,159.88 70.26,158.96 70.26,154.9 69.85,154.49 69.04,154.49 68.48,155.05 68.48,157.64 67.97,158.15 67.61,158.15 67.46,158 67.46,155.72 67.36,155.61 66.55,155.61 66.45,155.72 66.45,158.04 66.34,158.15 64.87,158.15 64.52,157.79 64.52,157.57 64.62,157.47 65.26,157.47 65.37,157.36 65.37,156.63 65.26,156.52 65.05,156.52 64.94,156.63 64.94,156.93 64.84,157.04 64.62,157.04 64.52,156.93 64.52,155.91 66.7,153.73 66.7,151.95 66.86,151.79 67.01,151.79 67.46,152.25 67.61,152.25 68.7,151.16 68.7,151.01 68.55,150.86 68.4,150.86 67.61,151.64 67.46,151.64 67.31,151.49 67.31,151.34 68.33,150.33 69.95,150.33 71.73,152.11 v1(72.28,152.11)
VPFE0_PCLK: length 56.1
  TOP w0.178: U10.53 56.71,152.99 57.63,153.91 57.63,154.52 v1(57.1,155.05) ; R31.1 49.85,162.38 v1(50.24,162.77)
  L08_SIG2 w0.107: v1(50.24,162.77) 50.32,162.69 54.27,162.69 54.36,162.6 54.36,162.47 54.27,162.37 51.27,162.37 51.18,162.28 51.18,162.15 51.27,162.05 54.27,162.05 54.36,161.96 54.36,161.83 54.27,161.73 51.27,161.73 51.18,161.64 51.18,161.51 51.27,161.41 54.27,161.41 54.36,161.32 54.36,161.19 54.27,161.09 51.27,161.09 51.18,161 51.18,160.87 51.27,160.77 54.27,160.77 54.36,160.68 54.36,160.55 54.27,160.45 51.27,160.45 51.18,160.36 51.18,160.23 51.27,160.13 54.27,160.13 54.36,160.04 54.36,159.91 54.27,159.81 51.27,159.81 51.18,159.72 51.18,159.59 51.27,159.49 54.27,159.49 54.36,159.4 54.36,159.06 54.27,158.97 53.03,158.97 52.93,158.88 52.93,158.74 53.03,158.65 54.27,158.65 54.36,158.56 54.36,157.68 55.3,156.75 56.77,156.75 57.1,156.42 v1(57.1,155.05)
VPFE0_VD: length 60.3
  TOP w0.178: U11.48 74.78,149.11 74.55,149.33 v1(74.55,150.88) ; R44.1 72.64,161.86 72.03,161.25 69.41,161.25 v1(69.09,161.57)
  L03_SIG1 w0.107: v1(74.55,150.88) 74.02,150.88 73.91,150.78 73.91,150.56 74.04,150.43 74.78,150.43 75.03,150.68 75.03,152.1 75.14,152.21 75.33,152.21 75.44,152.1 75.44,150.23 75.33,150.12 72.49,150.12 72.38,150.23 72.38,150.44 72.49,150.55 73.2,150.55 73.3,150.66 73.3,150.87 73.2,150.98 72.06,150.98 71.96,150.87 71.96,150.23 71.85,150.12 71.63,150.12 71.32,150.43 71.32,151.14 71.53,151.34 74.37,151.34 74.52,151.5 74.52,151.95 74.37,152.1 73.1,152.1 72.2,153 72.05,153 71.62,152.57 71.47,152.57 71.32,152.72 71.32,152.87 71.75,153.3 71.75,153.45 71.42,153.78 71.42,155.86 71.32,155.96 70.97,155.96 70.87,155.86 70.87,153.69 70.72,153.54 69.67,153.54 69.55,153.42 69.55,152.57 69.8,152.31 71.01,152.31 71.12,152.2 71.12,151.93 70.02,150.83 69.49,150.83 67.01,153.32 67.01,153.86 66.72,154.15 66.72,154.51 66.89,154.68 68.41,154.68 68.91,154.18 69.98,154.18 70.57,154.77 70.57,156.73 70.71,156.88 71.15,156.88 71.3,157.03 71.3,158.4 69.09,160.61 v1(69.09,161.57)
WKUP_I2C0_SCL: length 78.6
  TOP w0.178: J1.65 84.02,115.51 v1(83.97,115.46) ; R218.1 v1(80.65,69.16) ; U30.6 v1(70.57,51.64)
  BOTTOM w0.178: v1(83.97,115.46) 86.9,112.54 R393.1 86.82,111.33 86.82,110.19 86.18,109.56 86.18,96.1 81.18,91.09 81.18,69.69 v1(80.65,69.16) 80.14,68.65 80.14,55.1 78.68,53.64 72.57,53.64 v1(70.57,51.64)
WKUP_I2C0_SDA: length 78.7
  TOP w0.178: J1.63 85.1,114.97 83.3,114.97 v1(83,115.27) ; R216.1 v1(80.65,70.38) ; U30.5 v1(70.57,52.91)
  BOTTOM w0.178: v1(70.57,52.91) 71.74,54.08 78.42,54.08 79.71,55.37 79.71,69.43 v1(80.65,70.38) 80.65,91.33 85.78,96.45 85.78,109.71 85.29,110.19 84.12,110.19 83.89,110.43 R394.1 83.89,113.53 83,114.42 v1(83,115.27)
N19811491: length 3.2
  TOP w0.178: C42.2 25.4,158.73 25.87,159.2 U8.23
N19811520: length 3.5
  TOP w0.178: U8.18 25.15,161.7 24.14,162.71 R47.2
N19811540: length 5
  TOP w0.178: C32.1 25.09,166.97 25.5,166.56 25.5,164.02 25.82,163.7 U8.14
N19811568: length 4.5
  TOP w0.178: U8.17 26.66,162.16 25.25,162.16 24.49,162.92 24.49,163.91 24.23,164.17 C35.1
N19811570: length 5.6
  TOP w0.178: U8.7 29.94,168.14 C28.1 C29.1
N23276319: length 3.6
  BOTTOM w0.178: U41.11 R338.1
N23670479: length 1.6
  TOP w0.381: C204.1 R304.2
N23670482: length 1.6
  TOP w0.381: C196.1 R290.2
N23684707: length 3.3
  TOP w0.178: R101.2 37.9,136.04 37.36,136.59 C278.1
N23911217: length 4
  BOTTOM w0.178: R233.1 95.21,67.61 94.25,68.57 J17.31
N23911219: length 5.4
  BOTTOM w0.178: J17.29 94.62,69.37 95.15,68.84 95.15,68.52 R235.1
N23981776: length 2.4
  TOP w0.381: R226.2 R227.2 C147.2
N23985739: length 2.4
  TOP w0.381: C158.2 R245.2 R244.2
N23990208: length 3.2
  TOP w0.381: R244.1 25.02,51.48 R243.2 22.04,51.48 R247.2
N23990244: length 2.5
  TOP w0.381: R223.2 22.69,63.15 R225.2 25.02,63.15 R226.1
N24479449: length 2.4
  BOTTOM w0.381: R461.2 R460.2 C342.2
N24479767: length 3.2
  BOTTOM w0.381: R461.1 25.02,63.15 R462.2 22.04,63.15 R458.2
N24480253: length 2.5
  BOTTOM w0.381: R481.2 22.69,51.48 R480.2 24.12,51.41 R479.1
N24480259: length 2.4
  BOTTOM w0.381: R479.2 R478.2 C354.2
N24488350: length 1.6
  BOTTOM w0.381: C373.1 R514.2
N24488546: length 1.6
  BOTTOM w0.381: C380.1 R526.2
N24492127: length 1.6
  TOP w0.381: C183.1 R280.2
N24492135: length 1.6
  BOTTOM w0.381: C359.1 R488.2
N24492520: length 1.6
  TOP w0.381: R255.2 C168.1
N24492543: length 1.6
  BOTTOM w0.381: C366.1 R504.2
N24497380: length 2.4
  TOP w0.381: R196.2 R197.2 C118.2
N24497698: length 3.2
  TOP w0.381: R199.2 22.04,84.67 R195.2 25.02,84.67 R196.1
N24498184: length 2.5
  TOP w0.381: R175.2 22.69,96.34 R176.2 25.02,96.34 R177.1
N24498190: length 2.4
  TOP w0.381: C105.2 R178.2 R177.2
N24501627: length 2.4
  BOTTOM w0.381: R420.2 R419.2 C310.2
N24501939: length 3.2
  BOTTOM w0.381: R420.1 25.02,96.34 R421.2 22.04,96.34 R418.2
N24502423: length 2.5
  BOTTOM w0.381: R437.1 25.02,84.67 R438.2 22.69,84.67 R440.2
N24502429: length 2.4
  BOTTOM w0.381: C322.2 R436.2 R437.2
N24516386: length 1.6
  TOP w0.381: C89.1 R165.2
N24516394: length 1.6
  BOTTOM w0.381: C293.1 R398.2
N24516779: length 1.6
  TOP w0.381: C72.1 R143.2
N24516802: length 1.6
  BOTTOM w0.381: C301.1 R412.2
N24517434: length 1.6
  TOP w0.381: C64.1 R133.2
N24517442: length 1.6
  BOTTOM w0.381: R372.2 C279.1
N24517839: length 1.6
  TOP w0.381: C52.1 R109.2
N24517862: length 1.6
  BOTTOM w0.381: C286.1 R386.2
N24561941: length 1.6
  TOP w0.178: R50.1 44.55,160.72 44.81,160.45 U9.6
N24561944: length 1.6
  TOP w0.178: R51.1 45.72,160.68 45.46,160.43 U9.5
N24562809: length 3.5
  TOP w0.178: R56.2 C38.1 U9.8 U9.7
N24589481: length 10
  TOP w0.178: U2.40 23.58,186.31 v1(23.38,186.51) 23.66,186.51 24.08,186.93 R5.2
  BOTTOM w0.178: R535.2 R534.2 28.09,186.77 27.81,187.05 24.89,187.05 24.34,186.51 v1(23.38,186.51)
N24613389: length 2.2
  TOP w0.178: U15.18 R110.2
N24636980: length 1.7
  BOTTOM w0.178: U35.6 36.75,185.07 36.35,185.48 R315.1
N24637007: length 1.8
  BOTTOM w0.178: R323.1 36.24,180.34 36.75,180.85 U35.3
N24638437: length 1.5
  BOTTOM w0.178: U38.1 R326.2
N24673543: length 5.2
  TOP w0.178: U11.37 v1(80.28,147.03)
  BOTTOM w0.178: TP44.1 80.11,145.09 79.72,145.49 79.72,146.47 v1(80.28,147.03)
N24673545: length 3.8
  TOP w0.178: U11.40 v1(78.78,147.03)
  BOTTOM w0.178: v1(78.78,147.03) 78.27,146.52 78.27,145.01 TP45.1
N24673547: length 3.1
  TOP w0.178: U11.51 73.28,146.64 v1(72.75,146.11)
  BOTTOM w0.178: TP46.1 72.85,146.01 v1(72.75,146.11)
N24676160: length 7.4
  TOP w0.178: U10.3 56.21,136.94 v1(56.52,136.63)
  BOTTOM w0.178: TP41.1 54.94,135.97 55.12,136.15 56.03,136.15 v1(56.52,136.63)
N24676162: length 5
  TOP w0.178: v1(56.21,151.09) U10.54
  BOTTOM w0.178: v1(56.21,151.09) 56.77,151.65 TP32.1
N24733661: length 1.6
  BOTTOM w0.178: R314.1 37.65,185.52 37.25,185.11 U35.7
N24733666: length 1.3
  BOTTOM w0.178: U35.1 R321.1
N24736802: length 3.1
  TOP w0.178: R120.2 47.52,125.99 48.81,127.28 U14.2
N24788879: length 5.7
  BOTTOM w0.381: R327.1 C217.1 79.89,179.66 79.58,179.97 U37.7
N24793440: length 4.6
  BOTTOM w0.178: R213.1 U25.1 62.83,70.19 63.33,69.69 U25.7
N24805264: length 2.1
  BOTTOM w0.178: U43.18 69.94,154.91 70.32,154.53 R347.2
N24817584: length 4.6
  BOTTOM w0.178: U21.7 64.91,94.2 64.41,94.7 U21.1 R183.1
N24985508: length 6.2
  TOP w0.178: U13.6 R100.1 ; U13.6 25.55,138.57 25.78,138.34 26.59,138.34 26.85,138.08 U13.3 ; U13.6 25.55,140.04 25.27,140.32 R99.1
N24986462: length 1.1
  TOP w0.178: R104.1 C51.2
N24987908: length 1.2
  BOTTOM w0.178: R358.2 LD2.2
N24987961: length 3
  BOTTOM w0.178: LD2.1 Q2.3
N24990777: length 1.9
  BOTTOM w0.178: LD3.2 R367.2
N24990859: length 3.2
  BOTTOM w0.178: LD3.1 32.35,137.99 32.1,138.24 Q3.3
N24990930: length 1.3
  BOTTOM w0.178: LD1.2 R350.2
N24990935: length 1.5
  BOTTOM w0.178: LD1.1 Q1.3

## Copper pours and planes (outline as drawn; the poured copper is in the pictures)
DGND on L02_GND1: 1.02,10.84 1.02,22.53 6.03,22.53 6.29,22.78 6.29,29.83 6.03,30.08 1.02,30.08 1.02,38.91 5.91,38.91 6.16,39.16 6.16,46.08 5.91,46.34 1.02,46.34 1.02,55.35 5.91,55.35 6.16,55.61 6.16,62.34 5.91,62.59 1.02,62.59 1.02,71.61 5.97,71.61 6.22,71.86 6.22,78.72 5.97,78.98 1.02,78.98 1.02,87.87 5.91,87.87 6.16,88.12 6.16,95.11 5.91,95.36 1.02,95.36 1.02,104.25 6.03,104.25 6.29,104.5 6.29,111.43 6.03,111.68 1.02,111.68 1.02,120.63 5.97,120.63 6.22,120.89 6.22,127.74 5.97,128 1.02,128 1.02,198.17 1.33,198.48 81.43,198.48 81.81,198.1 81.81,190.74 82.09,190.46 86.93,190.46 87.19,190.71 87.19,192.12 87.5,192.43 97.17,192.43 97.47,192.13 97.47,190.8 97.82,190.46 101.37,190.46 101.6,190.23 101.6,10.52 101.09,10.02 1.84,10.02 ; 11 cut-outs
DGND on L04_GND2: 1.02,10.84 1.02,22.53 6.03,22.53 6.29,22.78 6.29,29.83 6.03,30.08 1.02,30.08 1.02,38.91 5.91,38.91 6.16,39.16 6.16,46.08 5.91,46.34 1.02,46.34 1.02,55.35 5.91,55.35 6.16,55.61 6.16,62.34 5.91,62.59 1.02,62.59 1.02,71.61 5.97,71.61 6.22,71.86 6.22,78.72 5.97,78.98 1.02,78.98 1.02,87.87 5.91,87.87 6.16,88.12 6.16,95.11 5.91,95.36 1.02,95.36 1.02,104.25 6.03,104.25 6.29,104.5 6.29,111.43 6.03,111.68 1.02,111.68 1.02,120.63 5.97,120.63 6.22,120.89 6.22,127.74 5.97,128 1.02,128 1.02,198.17 1.33,198.48 81.43,198.48 81.81,198.1 81.81,190.74 82.09,190.46 86.93,190.46 87.19,190.71 87.19,192.12 87.5,192.43 97.17,192.43 97.47,192.13 97.47,190.8 97.82,190.46 101.37,190.46 101.6,190.23 101.6,10.52 101.09,10.02 1.84,10.02 ; 3 cut-outs
DGND on L07_GND3: 1.02,10.84 1.02,22.53 6.03,22.53 6.29,22.78 6.29,29.83 6.03,30.08 1.02,30.08 1.02,38.91 5.91,38.91 6.16,39.16 6.16,46.08 5.91,46.34 1.02,46.34 1.02,55.35 5.91,55.35 6.16,55.61 6.16,62.34 5.91,62.59 1.02,62.59 1.02,71.61 5.97,71.61 6.22,71.86 6.22,78.72 5.97,78.98 1.02,78.98 1.02,87.87 5.91,87.87 6.16,88.12 6.16,95.11 5.91,95.36 1.02,95.36 1.02,104.25 6.03,104.25 6.29,104.5 6.29,111.43 6.03,111.68 1.02,111.68 1.02,120.63 5.97,120.63 6.22,120.89 6.22,127.74 5.97,128 1.02,128 1.02,198.17 1.33,198.48 81.43,198.48 81.81,198.1 81.81,190.74 82.09,190.46 86.93,190.46 87.19,190.71 87.19,192.12 87.5,192.43 97.17,192.43 97.47,192.13 97.47,190.8 97.82,190.46 101.37,190.46 101.6,190.23 101.6,10.52 101.09,10.02 1.84,10.02 ; 3 cut-outs
DGND on L08_SIG2: 1.02,10.84 1.02,22.53 6.03,22.53 6.29,22.78 6.29,29.83 6.03,30.08 1.02,30.08 1.02,38.91 5.91,38.91 6.16,39.16 6.16,46.08 5.91,46.34 1.02,46.34 1.02,55.35 5.91,55.35 6.16,55.61 6.16,62.34 5.91,62.59 1.02,62.59 1.02,71.61 5.97,71.61 6.22,71.86 6.22,78.72 5.97,78.98 1.02,78.98 1.02,87.87 5.91,87.87 6.16,88.12 6.16,95.11 5.91,95.36 1.02,95.36 1.02,104.25 6.03,104.25 6.29,104.5 6.29,111.43 6.03,111.68 1.02,111.68 1.02,120.63 5.97,120.63 6.22,120.89 6.22,127.74 5.97,128 1.02,128 1.02,198.17 1.33,198.48 81.43,198.48 81.81,198.1 81.81,190.74 82.09,190.46 86.93,190.46 87.19,190.71 87.19,192.12 87.5,192.43 97.17,192.43 97.47,192.13 97.47,190.8 97.82,190.46 101.37,190.46 101.6,190.23 101.6,10.52 101.09,10.02 1.84,10.02 ; 100 cut-outs
DGND on L09_GND4: 1.84,10.02 1.02,10.84 1.02,22.53 6.03,22.53 6.29,22.78 6.29,29.83 6.03,30.08 1.02,30.08 1.02,38.91 5.91,38.91 6.16,39.16 6.16,46.08 5.91,46.34 1.02,46.34 1.02,55.35 5.91,55.35 6.16,55.61 6.16,62.34 5.91,62.59 1.02,62.59 1.02,71.61 5.97,71.61 6.22,71.86 6.22,78.72 5.97,78.98 1.02,78.98 1.02,87.87 5.91,87.87 6.16,88.12 6.16,95.11 5.91,95.36 1.02,95.36 1.02,104.25 6.03,104.25 6.29,104.5 6.29,111.43 6.03,111.68 1.02,111.68 1.02,120.63 5.97,120.63 6.22,120.89 6.22,127.74 5.97,128 1.02,128 1.02,198.17 1.33,198.48 81.43,198.48 81.81,198.1 81.81,190.74 82.09,190.46 87.19,190.46 87.19,192.12 87.5,192.43 91.08,192.43 91.08,189.95 97.79,189.95 97.79,190.46 101.37,190.46 101.6,190.23 101.6,10.52 101.09,10.02 ; 13 cut-outs
VCC_1V8 on TOP: 90.49,79.29 93.85,79.29 94.11,79.55 94.11,81.33 94.11,81.33 94.11,82.41 94.34,82.63 96.65,82.63 96.77,82.51 96.77,78.09 96.65,77.96 90.49,77.96 90.36,78.09 90.36,79.17
VCC_1V8 on L06_PWR2: 48.18,132.06 81.02,132.06 81.52,131.56 81.52,87.44 82.23,86.72 95.92,86.72 96.3,86.34 96.3,76.32 96.01,76.03 77.3,76.03 76.69,76.64 76.69,121.17 76.09,121.77 54.62,121.77 54.36,122.03 54.36,125.74 53.87,126.22 42.72,126.22 42.32,126.62 42.32,133.71 37.15,133.71 36.6,134.25 36.6,164.19 36.96,164.54 47.05,164.54 47.34,164.26 47.34,132.9
VCC_3V3 on TOP: 94.49,44.79 100.26,44.79 100.47,45 100.47,47.99 100.31,48.16 98.07,48.16 97.83,47.92 97.83,46.04 97.74,45.96 94.51,45.96 94.44,45.88 94.44,44.84
VCC_3V3 on TOP: 64.9,47.8 67.31,47.8 67.44,47.67 67.44,46.46 67.31,46.34 64.9,46.34 64.77,46.46 64.77,47.67
VCC_3V3 on TOP: 13.26,137.32 15.26,137.32 15.48,137.1 15.48,132.64 15.28,132.44 13.18,132.44 13.04,132.58 13.04,137.1
VCC_3V3 on TOP: 68.52,109.9 70.77,109.9 70.92,109.75 70.92,108.7 70.79,108.57 68.52,108.57 68.39,108.69 68.39,109.77
VCC_3V3 on L05_PWR1: 13.07,186.97 13.07,100.64 13.77,99.94 55.63,99.94 57.55,98.02 57.55,72.59 48.67,63.71 48.67,10.75 49.4,10.02 101.09,10.02 101.6,10.52 101.6,190.23 101.35,190.48 82.17,190.48 82.17,184.35 36.96,184.35 36.45,184.86 36.45,187.21 36.17,187.49 13.58,187.49
VCC_5V0 on TOP: 42.32,124.44 46.51,124.44 46.76,124.19 46.76,123.12 46.51,122.87 42.32,122.87 42.06,123.12 42.06,124.19
VCC_5V0 on TOP: 64.96,112.06 66.61,112.06 66.74,111.93 66.74,110.41 66.36,110.03 65.59,110.03 65.51,110.11 65.51,111.14 65.42,111.23 64.96,111.23 64.83,111.36 64.83,111.93
VCC_5V0 on TOP: 62.67,38.27 65.28,38.27 65.41,38.15 65.41,37.03 65.32,36.94 62.64,36.94 62.55,37.04 62.55,38.15
VCC_5V0 on TOP: 65.21,103.74 66.99,103.74 67.12,103.61 67.12,101.77 66.99,101.65 65.21,101.65 65.09,101.77 65.09,103.61
VCC_5V0 on TOP: 62.1,52.69 63.69,52.69 63.82,52.56 63.82,51.48 63.69,51.35 62.1,51.35 61.98,51.48 61.98,52.56
VCC_5V0 on TOP: 90.23,69.2 90.23,70.04 90.47,70.28 98.42,70.28 98.68,70.02 98.68,68.05 98.48,67.85 95.58,67.85 95.29,68.14 95.29,69.16 95.12,69.32 92.84,69.32 92.53,69.02 90.41,69.02
VCC_5V0 on TOP: 66.5,191.47 63.93,191.47 63.7,191.7 63.7,193.48 63.97,193.74 66.5,193.74
VCC_5V0 on TOP: 50.09,74.99 55.65,74.99 55.93,74.71 55.93,73.39 55.78,73.24 50.09,73.24 49.91,73.41 49.91,74.81
VCC_5V0 on L05_PWR1: 73.81,112.92 80.38,112.92 80.68,113.22 80.68,138.63 81,138.95 82.37,138.95 82.73,139.3 82.73,147.49 82.33,147.9 61.93,147.9 61.75,147.71 61.75,140.24 62.08,139.91 73.05,139.91 73.5,139.45 73.5,113.23
VCC_5V0 on L06_PWR2: 101.35,190.48 101.6,190.23 101.6,138.98 101.35,138.73 78.61,138.73 78.11,139.23 78.11,150.85 77.47,151.49 55.69,151.49 55.25,151.94 55.25,171.18 55.6,171.53 75.46,171.53 75.87,171.94 75.87,181.14 75.29,181.72 67.97,181.72 67.94,181.69 60.92,181.69 60.65,181.96 60.65,198.05 61.09,198.48 81.41,198.48 81.79,198.1 81.79,190.74 82.04,190.48
VCC_5V0 on L06_PWR2: 76.17,120.96 76.17,76.19 76.81,75.55 98.05,75.55 98.5,75.1 98.5,65.9 98.18,65.58 81.83,65.58 81.14,64.9 81.14,51.53 81.57,51.1 101.35,51.1 101.6,50.85 101.6,10.52 101.09,10.02 42.8,10.02 42.29,10.53 42.29,102.94 42.49,103.14 61.24,103.14 61.65,103.56 61.65,111.75 61.09,112.31 42.49,112.31 42.29,112.51 42.29,125.08 42.73,125.52 53.59,125.52 53.85,125.27 53.85,121.52 54.15,121.22 75.92,121.22
VCC_12V on TOP: 90.63,93.3 90.45,93.48 90.45,95.54 90.58,95.66 100.94,95.66 101.14,95.46 101.14,93.53 100.91,93.3
VCC_12V on BOTTOM: 84.42,57.77 84.43,57.75 84.44,57.73 84.59,57.58 84.61,57.57 84.63,57.56 87.41,57.56 87.43,57.56 87.44,57.55 87.54,57.45 87.55,57.44 87.55,57.42 87.55,55.71 87.55,55.69 87.54,55.67 87.44,55.57 87.43,55.56 87.41,55.56 83.69,55.56 83.64,55.56 83.58,55.56 81.48,55.56 81.48,63.81 82.02,64.35 85.93,64.35 85.95,64.34 85.97,64.33 86.19,64.11 86.2,64.09 86.21,64.07 86.21,61.78 86.2,61.76 86.19,61.74 86.04,61.59 86.03,61.58 86.01,61.58 84.59,61.58 84.57,61.57 84.55,61.56 84.44,61.45 84.43,61.43 84.42,61.41 84.42,59.58 84.42,59.55 84.4,59.53 84.32,59.49 84.29,59.48 84.27,59.49 83.6,59.13 84.27,58.77 84.29,58.78 84.32,58.77 84.4,58.73 84.42,58.71
VCC_12V on BOTTOM: 97.35,54.9 97.33,54.9 97.32,54.91 96.69,55.54 96.67,55.55 96.65,55.56 95.18,55.56 95.15,55.56 95.13,55.58 94.77,55.79 94.4,55.58 94.38,55.56 94.36,55.56 90.78,55.56 90.76,55.56 90.74,55.57 90.64,55.67 90.63,55.69 90.63,55.71 90.63,57.29 90.63,57.31 90.64,57.33 90.89,57.58 90.91,57.59 90.93,57.59 99.06,57.59 99.08,57.59 99.1,57.58 99.27,57.4 99.28,57.39 99.29,57.37 99.29,55 99.28,54.98 99.27,54.96 99.23,54.91 99.21,54.9 99.19,54.9
VCC_12V on BOTTOM: 24.25,168.13 24.23,168.13 24.22,168.15 23.99,168.37 23.98,168.39 23.98,168.41 23.98,170.38 23.98,170.39 23.99,170.41 24.42,170.84 24.43,170.86 24.43,170.87 24.43,171.67 24.43,171.69 24.42,171.7 24.3,171.82 24.28,171.83 24.27,171.84 22.26,171.84 22.25,171.84 22.1,171.86 21.95,171.84 21.94,171.84 21.84,171.84 21.82,171.83 21.81,171.82 21.67,171.68 21.66,171.66 21.65,171.64 21.65,170.88 21.65,170.87 21.64,170.85 21.52,170.74 21.51,170.73 21.49,170.72 19.96,170.72 19.94,170.73 19.91,170.76 19.91,172.65 19.92,172.67 19.93,172.69 20.11,172.87 20.13,172.88 20.15,172.89 25.5,172.89 25.52,172.88 25.54,172.87 25.69,172.72 25.7,172.7 25.7,172.68 25.7,168.2 25.7,168.18 25.69,168.17 25.67,168.15 25.65,168.13 25.63,168.13
VCC_12V on L06_PWR2: 3.4,155.67 3.4,134.41 4.06,133.75 35.75,133.75 36.11,134.11 36.11,164.63 36.45,164.97 47.49,164.97 47.88,164.57 47.88,133.23 48.48,132.63 81.51,132.63 82.01,132.13 82.01,87.95 82.55,87.41 96.43,87.41 96.93,86.91 96.93,76.37 97.28,76.02 98.45,76.02 98.93,75.54 98.93,65.64 98.42,65.13 81.98,65.13 81.53,64.69 81.53,55.83 81.85,55.51 88.47,55.51 88.49,55.53 93.99,55.53 94.36,55.16 94.36,51.74 94.61,51.49 101.35,51.49 101.6,51.74 101.6,137.93 101.29,138.24 78.23,138.24 77.51,138.96 77.51,150.41 76.97,150.96 55.12,150.96 54.61,151.46 54.61,170.99 54.01,171.59 33.13,171.59 32.99,171.72 32.99,172.2 32.84,172.35 19.88,172.35 19.56,172.03 19.56,156.37 19.34,156.15 3.88,156.15
VCC_12V_CON on L06_PWR2: 3.38,172.08 3.38,156.87 3.69,156.56 18.77,156.56 19.09,156.88 19.09,171.86 18.58,172.36 3.66,172.36
VCC_12V_FPD on BOTTOM: 12.72,170.7 12.7,170.7 12.69,170.71 12.59,170.81 12.58,170.82 12.57,170.84 12.57,171.28 7.01,171.28 7.01,172.51 7.01,172.51 7.01,176.34 7.01,176.36 7.03,176.37 7.12,176.47 7.14,176.48 7.16,176.48 10.44,176.48 10.46,176.48 10.48,176.47 10.59,176.36 10.6,176.35 10.6,176.33 10.6,175.09 10.6,175.07 10.61,175.05 10.79,174.88 10.8,174.87 10.82,174.86 13.92,174.86 14.32,174.46 14.32,172.4 15.73,172.4 15.75,172.39 15.76,172.38 15.91,172.24 15.92,172.22 15.93,172.2 15.93,170.87 15.92,170.85 15.91,170.83 15.79,170.71 15.77,170.7 15.75,170.7
VCC_12V_FPD on L06_PWR2: 3.93,189.67 19.11,189.67 19.11,173.33 18.73,172.96 3.72,172.96 3.36,173.32 3.36,189.09
VCC_CAM_3V3 on TOP: 73.15,179.88 74.55,179.88 74.68,179.75 74.68,176.39 74.55,176.26 73.15,176.26 73.03,176.39 73.03,179.75
